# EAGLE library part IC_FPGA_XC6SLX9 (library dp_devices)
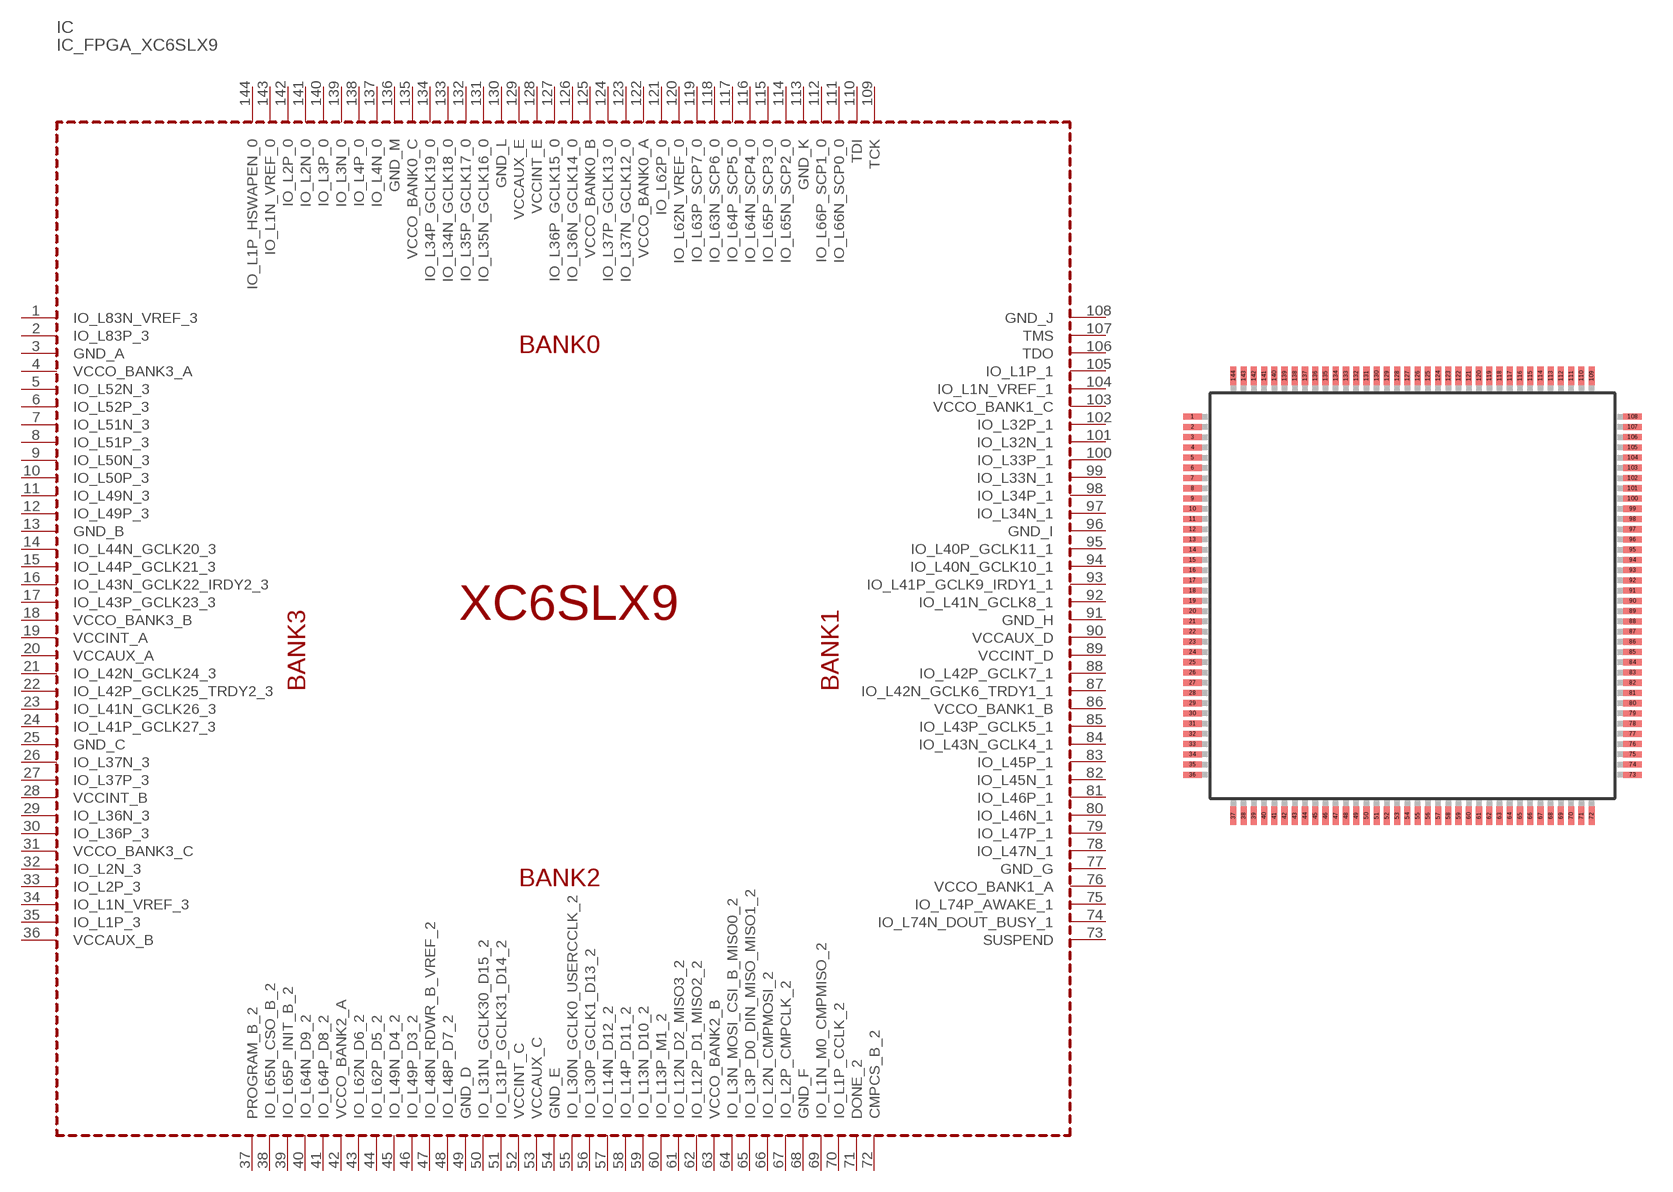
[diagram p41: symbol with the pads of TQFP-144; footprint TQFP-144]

Designator prefix IC

## IC_FPGA_XC6SLX93TQG144C  [TQFP-144]
1  IO_L83N_VREF_3
2  IO_L83P_3
3  GND_A  pwr
4  VCCO_BANK3_A  pwr
5  IO_L52N_3
6  IO_L52P_3
7  IO_L51N_3
8  IO_L51P_3
9  IO_L50N_3
10  IO_L50P_3
11  IO_L49N_3
12  IO_L49P_3
13  GND_B  pwr
14  IO_L44N_GCLK20_3
15  IO_L44P_GCLK21_3
16  IO_L43N_GCLK22_IRDY2_3
17  IO_L43P_GCLK23_3
18  VCCO_BANK3_B  pwr
19  VCCINT_A  pwr
20  VCCAUX_A  pwr
21  IO_L42N_GCLK24_3
22  IO_L42P_GCLK25_TRDY2_3
23  IO_L41N_GCLK26_3
24  IO_L41P_GCLK27_3
25  GND_C
26  IO_L37N_3
27  IO_L37P_3
28  VCCINT_B  pwr
29  IO_L36N_3
30  IO_L36P_3
31  VCCO_BANK3_C  pwr
32  IO_L2N_3
33  IO_L2P_3
34  IO_L1N_VREF_3
35  IO_L1P_3
36  VCCAUX_B  pwr
37  PROGRAM_B_2
38  IO_L65N_CSO_B_2
39  IO_L65P_INIT_B_2
40  IO_L64N_D9_2
41  IO_L64P_D8_2
42  VCCO_BANK2_A  pwr
43  IO_L62N_D6_2
44  IO_L62P_D5_2
45  IO_L49N_D4_2
46  IO_L49P_D3_2
47  IO_L48N_RDWR_B_VREF_2
48  IO_L48P_D7_2
49  GND_D  pwr
50  IO_L31N_GCLK30_D15_2
51  IO_L31P_GCLK31_D14_2
52  VCCINT_C  pwr
53  VCCAUX_C  pwr
54  GND_E  pwr
55  IO_L30N_GCLK0_USERCCLK_2
56  IO_L30P_GCLK1_D13_2
57  IO_L14N_D12_2
58  IO_L14P_D11_2
59  IO_L13N_D10_2
60  IO_L13P_M1_2
61  IO_L12N_D2_MISO3_2
62  IO_L12P_D1_MISO2_2
63  VCCO_BANK2_B  pwr
64  IO_L3N_MOSI_CSI_B_MISO0_2
65  IO_L3P_D0_DIN_MISO_MISO1_2
66  IO_L2N_CMPMOSI_2
67  IO_L2P_CMPCLK_2
68  GND_F  pwr
69  IO_L1N_M0_CMPMISO_2
70  IO_L1P_CCLK_2
71  DONE_2
72  CMPCS_B_2
73  SUSPEND
74  IO_L74N_DOUT_BUSY_1
75  IO_L74P_AWAKE_1
76  VCCO_BANK1_A  pwr
77  GND_G  pwr
78  IO_L47N_1
79  IO_L47P_1
80  IO_L46N_1
81  IO_L46P_1
82  IO_L45N_1
83  IO_L45P_1
84  IO_L43N_GCLK4_1
85  IO_L43P_GCLK5_1
86  VCCO_BANK1_B  pwr
87  IO_L42N_GCLK6_TRDY1_1
88  IO_L42P_GCLK7_1
89  VCCINT_D  pwr
90  VCCAUX_D  pwr
91  GND_H  pwr
92  IO_L41N_GCLK8_1
93  IO_L41P_GCLK9_IRDY1_1
94  IO_L40N_GCLK10_1
95  IO_L40P_GCLK11_1
96  GND_I  pwr
97  IO_L34N_1
98  IO_L34P_1
99  IO_L33N_1
100  IO_L33P_1
101  IO_L32N_1
102  IO_L32P_1
103  VCCO_BANK1_C  pwr
104  IO_L1N_VREF_1
105  IO_L1P_1
106  TDO
107  TMS
108  GND_J  pwr
109  TCK
110  TDI
111  IO_L66N_SCP0_0
112  IO_L66P_SCP1_0
113  GND_K  pwr
114  IO_L65N_SCP2_0
115  IO_L65P_SCP3_0
116  IO_L64N_SCP4_0
117  IO_L64P_SCP5_0
118  IO_L63N_SCP6_0
119  IO_L63P_SCP7_0
120  IO_L62N_VREF_0
121  IO_L62P_0
122  VCCO_BANK0_A  pwr
123  IO_L37N_GCLK12_0
124  IO_L37P_GCLK13_0
125  VCCO_BANK0_B  pwr
126  IO_L36N_GCLK14_0
127  IO_L36P_GCLK15_0
128  VCCINT_E  pwr
129  VCCAUX_E  pwr
130  GND_L  pwr
131  IO_L35N_GCLK16_0
132  IO_L35P_GCLK17_0
133  IO_L34N_GCLK18_0
134  IO_L34P_GCLK19_0
135  VCCO_BANK0_C  pwr
136  GND_M  pwr
137  IO_L4N_0
138  IO_L4P_0
139  IO_L3N_0
140  IO_L3P_0
141  IO_L2N_0
142  IO_L2P_0
143  IO_L1N_VREF_0
144  IO_L1P_HSWAPEN_0

## Footprint TQFP-144 (pad centres in mm)
smd 0.9 x 0.3: 1 -10.75,8.75; 2 -10.75,8.25; 3 -10.75,7.75; 4 -10.75,7.25; 5 -10.75,6.75; 6 -10.75,6.25; 7 -10.75,5.75; 8 -10.75,5.25; 9 -10.75,4.75; 10 -10.75,4.25; 11 -10.75,3.75; 12 -10.75,3.25; 13 -10.75,2.75; 14 -10.75,2.25; 15 -10.75,1.75; 16 -10.75,1.25; 17 -10.75,0.75; 18 -10.75,0.25; 19 -10.75,-0.25; 20 -10.75,-0.75; 21 -10.75,-1.25; 22 -10.75,-1.75; 23 -10.75,-2.25; 24 -10.75,-2.75; 25 -10.75,-3.25; 26 -10.75,-3.75; 27 -10.75,-4.25; 28 -10.75,-4.75; 29 -10.75,-5.25; 30 -10.75,-5.75; 31 -10.75,-6.25; 32 -10.75,-6.75; 33 -10.75,-7.25; 34 -10.75,-7.75; 35 -10.75,-8.25; 36 -10.75,-8.75; 73 10.75,-8.75; 74 10.75,-8.25; 75 10.75,-7.75; 76 10.75,-7.25; 77 10.75,-6.75; 78 10.75,-6.25; 79 10.75,-5.75; 80 10.75,-5.25; 81 10.75,-4.75; 82 10.75,-4.25; 83 10.75,-3.75; 84 10.75,-3.25; 85 10.75,-2.75; 86 10.75,-2.25; 87 10.75,-1.75; 88 10.75,-1.25; 89 10.75,-0.75; 90 10.75,-0.25; 91 10.75,0.25; 92 10.75,0.75; 93 10.75,1.25; 94 10.75,1.75; 95 10.75,2.25; 96 10.75,2.75; 97 10.75,3.25; 98 10.75,3.75; 99 10.75,4.25; 100 10.75,4.75; 101 10.75,5.25; 102 10.75,5.75; 103 10.75,6.25; 104 10.75,6.75; 105 10.75,7.25; 106 10.75,7.75; 107 10.75,8.25; 108 10.75,8.75
smd 0.3 x 0.9: 37 -8.75,-10.75; 38 -8.25,-10.75; 39 -7.75,-10.75; 40 -7.25,-10.75; 41 -6.75,-10.75; 42 -6.25,-10.75; 43 -5.75,-10.75; 44 -5.25,-10.75; 45 -4.75,-10.75; 46 -4.25,-10.75; 47 -3.75,-10.75; 48 -3.25,-10.75; 49 -2.75,-10.75; 50 -2.25,-10.75; 51 -1.75,-10.75; 52 -1.25,-10.75; 53 -0.75,-10.75; 54 -0.25,-10.75; 55 0.25,-10.75; 56 0.75,-10.75; 57 1.25,-10.75; 58 1.75,-10.75; 59 2.25,-10.75; 60 2.75,-10.75; 61 3.25,-10.75; 62 3.75,-10.75; 63 4.25,-10.75; 64 4.75,-10.75; 65 5.25,-10.75; 66 5.75,-10.75; 67 6.25,-10.75; 68 6.75,-10.75; 69 7.25,-10.75; 70 7.75,-10.75; 71 8.25,-10.75; 72 8.75,-10.75; 109 8.75,10.75; 110 8.25,10.75; 111 7.75,10.75; 112 7.25,10.75; 113 6.75,10.75; 114 6.25,10.75; 115 5.75,10.75; 116 5.25,10.75; 117 4.75,10.75; 118 4.25,10.75; 119 3.75,10.75; 120 3.25,10.75; 121 2.75,10.75; 122 2.25,10.75; 123 1.75,10.75; 124 1.25,10.75; 125 0.75,10.75; 126 0.25,10.75; 127 -0.25,10.75; 128 -0.75,10.75; 129 -1.25,10.75; 130 -1.75,10.75; 131 -2.25,10.75; 132 -2.75,10.75; 133 -3.25,10.75; 134 -3.75,10.75; 135 -4.25,10.75; 136 -4.75,10.75; 137 -5.25,10.75; 138 -5.75,10.75; 139 -6.25,10.75; 140 -6.75,10.75; 141 -7.25,10.75; 142 -7.75,10.75; 143 -8.25,10.75; 144 -8.75,10.75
